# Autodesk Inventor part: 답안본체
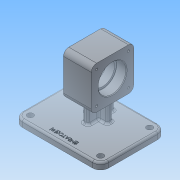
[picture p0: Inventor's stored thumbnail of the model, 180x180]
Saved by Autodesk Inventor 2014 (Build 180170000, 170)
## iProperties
Created: 2020-11
Part Number: 답안본체
Material: 일반
Document SubType Name: Modeling
Designer: NET
Density: 1 g/cm^3
Appearance: 기본값
Author: NET
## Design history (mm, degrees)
sketch "스케치1"
  geometry: L1 (-32, -32)-(32, -32); L2 (32, -32)-(32, 32); L3 (32, 32)-(-32, 32); L4 (-32, 32)-(-32, -32); L5 (-32, -32)-(32, 32); L6 (32, -32)-(-32, 32); 1 further point
  constraints: 12 end point, 2 midpoint, 2 parallel, 1 horizontal, 1 perpendicular
  dimensions: "d0" = 64 distance of L2.end L3.end; "d1" = 64 distance of L1.end L2.end
extrude "돌출1" new body sketch "스케치1" distance "d2" = 21; taper "d4" = 0 deg; dims "d3" = 21, "d5" = 0
sketch "스케치2"
  geometry: C1 r 18 at (0, 0); 1 further point
  constraints: 1 centre point, 1 coincident
  dimensions: "d6" = 36 diameter of C1
extrude "돌출2" cut sketch "스케치2" stored distance "d7" = 21; taper "d8" = 0 deg
sketch "스케치4"
  geometry: C1 r 18 at (0, 0) reference; C2 r 21 at (0, 0)
  constraints: 1 centre point, 1 coincident
  dimensions: "d9" = 42 diameter of C2
extrude "돌출3" cut sketch "스케치4" distance "d10" = 15; taper "d11" = 0 deg
sketch "스케치5"
  geometry: C1 r 18 at (0, 0) reference; C2 r 21 at (0, 0)
  constraints: 1 centre point, 1 coincident
  dimensions: "d12" = 42 diameter of C2
extrude "돌출4" cut sketch "스케치5" distance "d13" = 15; taper "d14" = 0 deg
node "작업 평면1"
sketch "스케치6"
  geometry: L1 (-44, 68)-(86, 68); L2 (86, 68)-(86, -30); L3 (86, -30)-(-44, -30); L4 (-44, -30)-(-44, 68); L5 (42, 64)-(42, 0) reference; 1 further point
  constraints: 8 end point, 2 parallel, 1 horizontal, 1 perpendicular
  dimensions: "d17" = 130 distance of L1.start L1.end; "d18" = 98 distance of L1.end L2.end; "d49" = 65 distance from line of L2 point (21, 32); "d50" = 62 distance from line of L3 point (21, 32)
extrude "돌출5" join sketch "스케치6" distance "d20" = 10; taper "d21" = 0 deg
fillet "모깎기1" dims "d22" = 8
sketch "스케치7"
  geometry: L1 (38, 28)-(4, 28); L2 (4, 28)-(4, 36); L3 (4, 36)-(38, 36); L4 (38, 36)-(38, 28); L5 (38, 28)-(4, 36); L6 (4, 28)-(38, 36); L7 (17, 12)-(25, 12); L8 (25, 12)-(25, 52); L9 (25, 52)-(17, 52); L10 (17, 52)-(17, 12); L11 (17, 12)-(25, 52); L12 (25, 12)-(17, 52); 1 further point
  constraints: 24 end point, 4 midpoint, 4 parallel, 2 horizontal, 2 perpendicular
  dimensions: "d23" = 8 distance of L8.end L9.end; "d24" = 8 distance of L1.end L2.end; "d25" = 40 distance between parallel lines of L9 L7; "d26" = 34 distance between parallel lines of L4 L2
extrude "돌출6" join sketch "스케치7" stored distance "d27" = 10; taper "d28" = 0 deg
fillet "모깎기2" dims "d29" = 12
sketch "스케치8"
  geometry: A1 r 12 centre (-32, -18) between (-44, -18) and (-32, -30) reference; A2 r 12 centre (74, -18) between (74, -30) and (86, -18) reference; A3 r 12 centre (74, 56) between (86, 56) and (74, 68) reference; A4 r 12 centre (-32, 56) between (-32, 68) and (-44, 56) reference; 5 further points
  constraints: 4 coincident
hole "구멍1" sketch "스케치8" at (-32, 56), (74, 56), (74, -18), (-32, -18) diameter "d30" = 9; stored, may be unused: countersink angle "d34" = 90 deg, drill point angle "d36" = 118 deg; dims "d31" = 6, "d32" = 4, "d33" = 2, "d35" = 8
fillet "모깎기3" dims "d37" = 3
fillet "모깎기4" dims "d38" = 0.3
chamfer "모따기1" distance "d39" = 1; stored, may be unused: second distance "d40" = 2, angle "d41" = 45 deg
fillet "모깎기5" dims "d42" = 3
fillet "모깎기6" dims "d43" = 3
fillet "모깎기7" dims "d44" = 3
sketch "스케치9"
  geometry: L1 (-44, 56)-(-44, -18) reference; L2 (-32, -30)-(74, -30) reference; 2 further points
  constraints: 1 other
  dimensions: "d45" = 65 distance from line of L1 point (21, -20); "d46" = 10 distance from line of L2 point (21, -20)
feature "엠보싱1" sketch "스케치9" dims "d0" = 64, "d1" = 64, "d47" = 0.5, "d48" = 0
sketch "스케치10"
  geometry: A1 r 8 centre (24, 24) between (32, 24) and (24, 32) reference; A2 r 8 centre (-24, 24) between (-24, 32) and (-32, 24) reference; A3 r 8 centre (-24, -24) between (-32, -24) and (-24, -32) reference; A4 r 8 centre (24, -24) between (24, -32) and (32, -24) reference; 4 further points
  constraints: 4 coincident
hole "구멍2" sketch "스케치10" at (-24, -24), (-24, 24), (24, 24), (24, -24) diameter "d51" = 3.242; stored, may be unused: countersink angle "d55" = 90 deg, drill point angle "d57" = 118 deg; dims "d52" = 8, "d53" = 4, "d54" = 2, "d56" = 10
sketch "스케치11"
  geometry: A1 r 8 centre (-24, 24) between (-24, 32) and (-32, 24) reference; A2 r 8 centre (-24, -24) between (-32, -24) and (-24, -32) reference; A3 r 8 centre (24, -24) between (24, -32) and (32, -24) reference; A4 r 8 centre (24, 24) between (32, 24) and (24, 32) reference; 4 further points
  constraints: 4 coincident
hole "구멍3" sketch "스케치11" at (-24, 24), (24, 24), (24, -24), (-24, -24) diameter "d58" = 3.242; stored, may be unused: countersink angle "d62" = 90 deg, drill point angle "d64" = 118 deg; dims "d59" = 8, "d60" = 4, "d61" = 2, "d63" = 10
node "솔리드1"
other parameters: "d15" = -102
